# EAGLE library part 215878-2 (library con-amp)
AMP connector
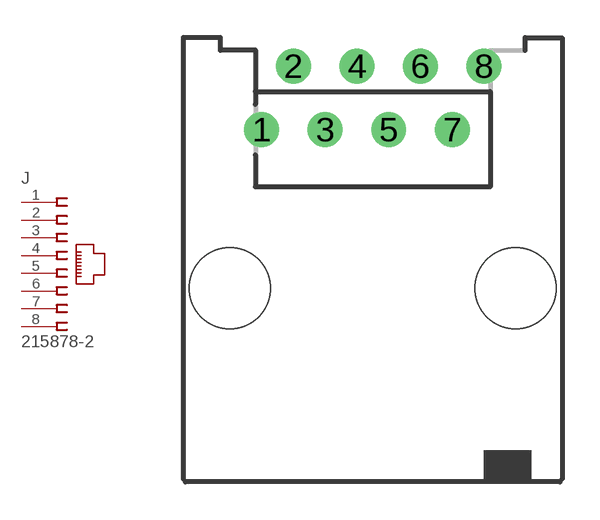
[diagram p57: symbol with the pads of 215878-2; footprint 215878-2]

Designator prefix J

## 215878-2 (OC_FARNELL: unknown; OC_NEWARK: unknown)  [215878-2]
1  1  pas
2  2  pas
3  3  pas
4  4  pas
5  5  pas
6  6  pas
7  7  pas
8  8  pas

## Footprint 215878-2 (pad centres in mm)
Modular Jack Keyed
drill 0.889 round: 1 -4.445,6.35; 2 -3.175,8.89; 3 -1.905,6.35; 4 -0.635,8.89; 5 0.635,6.35; 6 1.905,8.89; 7 3.175,6.35; 8 4.445,8.89
hole 3.251 at -5.715,0
hole 3.251 at 5.715,0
